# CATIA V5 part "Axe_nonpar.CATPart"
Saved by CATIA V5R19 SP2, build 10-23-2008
Part number: Axe
Bounding box of the stored display mesh (mm): x -6 to 6, y -22.75 to 54.75, z -6 to 6
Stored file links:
  F:\Projet CAO\pièces et assemblages\mécanisme 577\577-SaintAime\577-SaintAime\Axe_nonpar.CATPart
  C:\Users\Tilou\Documents\Cours M1\Conception\conception fauroux\Projet CAO\pièces et assemblages\mécanisme 577\mecanisme 577.CATProduct
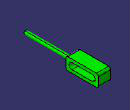
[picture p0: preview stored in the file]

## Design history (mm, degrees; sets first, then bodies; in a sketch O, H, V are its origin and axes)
Set1
  Point1: (0, 38.75, 3)
  Point2: (0, 38.75, -3)
Body1 (main body)
  Sketch1 on yz-plane, origin (0, 0, 0), H (0, 1, 0), V (0, 0, 1)
    point P1 (-22.75, 0)
    line L1 (-22.75, 0) -> (-22.75, 2)
    line L2 (-22.75, 2) -> (20.75, 2)
    line L3 (20.75, 2) -> (20.75, 3)
    point P4 (20.75, 3)
    line L4 (20.75, 3) -> (22.75, 3.7279)
    line L5 (22.75, 3.7279) -> (22.75, 0)
    point P6 (22.75, 0)
    line L6 (22.75, 0) -> (-22.75, 0)
    angle L4 L5 = 70
    distance L2 L6 = 2
    distance L3 L1 = 43.5
    distance L3 L5 = 2
    distance P4 L6 = 3
    coincidence: P1 H, P6 H
    vertical: L1 V, L3 V, L5 V
    horizontal: L2 H, L6 H
    symmetry: L1 L5 V
  Shaft1: profile Sketch1, axis Sketch1.L6, angle 360
  Sketch2 on yz-plane, origin (0, 0, 0), H (0, 1, 0), V (0, 0, 1)
    arc A1 centre (24.75, 4) radius 2 from (22.75, 4) to (24.75, 6) cw
    line L1 (24.75, 6) -> (52.75, 6)
    arc A2 centre (52.75, 4) radius 2 from (52.75, 6) to (54.75, 4) cw
    line L2 (54.75, 4) -> (54.75, -4)
    arc A3 centre (52.75, -4) radius 2 from (54.75, -4) to (52.75, -6) cw
    line L3 (52.75, -6) -> (24.75, -6)
    arc A4 centre (24.75, -4) radius 2 from (24.75, -6) to (22.75, -4) cw
    line L4 (22.75, 4) -> (22.75, -4)
    construction line L5 (28.75, 0) -> (48.75, 0)
    point P13 (28.75, 0)
    point P14 (48.75, 0)
    line L6 (28.75, 3) -> (48.75, 3)
    line L7 (48.75, -3) -> (28.75, -3)
    arc A5 centre (48.75, 0) radius 3 from (48.75, 3) to (48.75, -3) cw
    arc A6 centre (28.75, 0) radius 3 from (28.75, -3) to (28.75, 3) cw
    axis line L8 (38.75, 17.8201) -> (38.75, -16.8608)
    reference intersected line E1 (22.75, 4.2279) -> (22.75, -4.2279) from face of Shaft1 from Sketch1.L5
    distance L5 L6 = 3
    radius A2 = 2
    radius A3 = 2
    radius A1 = 2
    radius A4 = 2
    distance P13 P14 = 20
    distance L8 L2 = 16
    distance L5 L1 = 6
    tangency: L1 A1, A2 L1, A3 L2, L3 A3, A4 L3, A4 L4, L2 A2, L4 A1, A5 L6, A6 L6, A5 L7, A6 L7
    vertical: L4 V, L2 V, L8 V
    horizontal: L1 H, L5 H, L3 H
    coincidence: P13 H, L4 E1
    symmetry: P14 P13 L8, L4 L2 L8, L3 L1 L5
  Pad1: profile Sketch2, direction (1, 0, 0), length 6, mirrored extent
  Chamfer1: length 0.5, angle 45, on edge [face of Shaft1 from Sketch1.L1 | face of Shaft1 from Sketch1.L2]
